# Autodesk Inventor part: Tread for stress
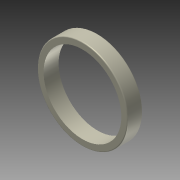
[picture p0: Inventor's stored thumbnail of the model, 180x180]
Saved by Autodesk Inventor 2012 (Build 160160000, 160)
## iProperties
Created: 2011-01
Part Number: Tread for stress
Document SubType Name: Modeling
Designer: Alex
Density: 0.93 g/cm^3
Material: Rubber_65A_durometer_urethane_rubber
Mass: 110.985 g
Surface Area: 314.143 cm^2
Volume: 119.339 cm^3
Author: Alex
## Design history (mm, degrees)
sketch "Sketch1"
  geometry: C1 r 65.608 at (0, 0); C2 r 76.2 at (0, 0); 1 further point
  constraints: 2 centre point
  dimensions: "d0" = 131.2164 diameter of C1; "d1" = 152.4 diameter of C2
extrude "Extrusion1" new body sketch "Sketch1" distance "d2" = 25.4; taper "d3" = 0 deg
fillet "Fillet1" dims "d4" = 1.5875
body "Solid1"
